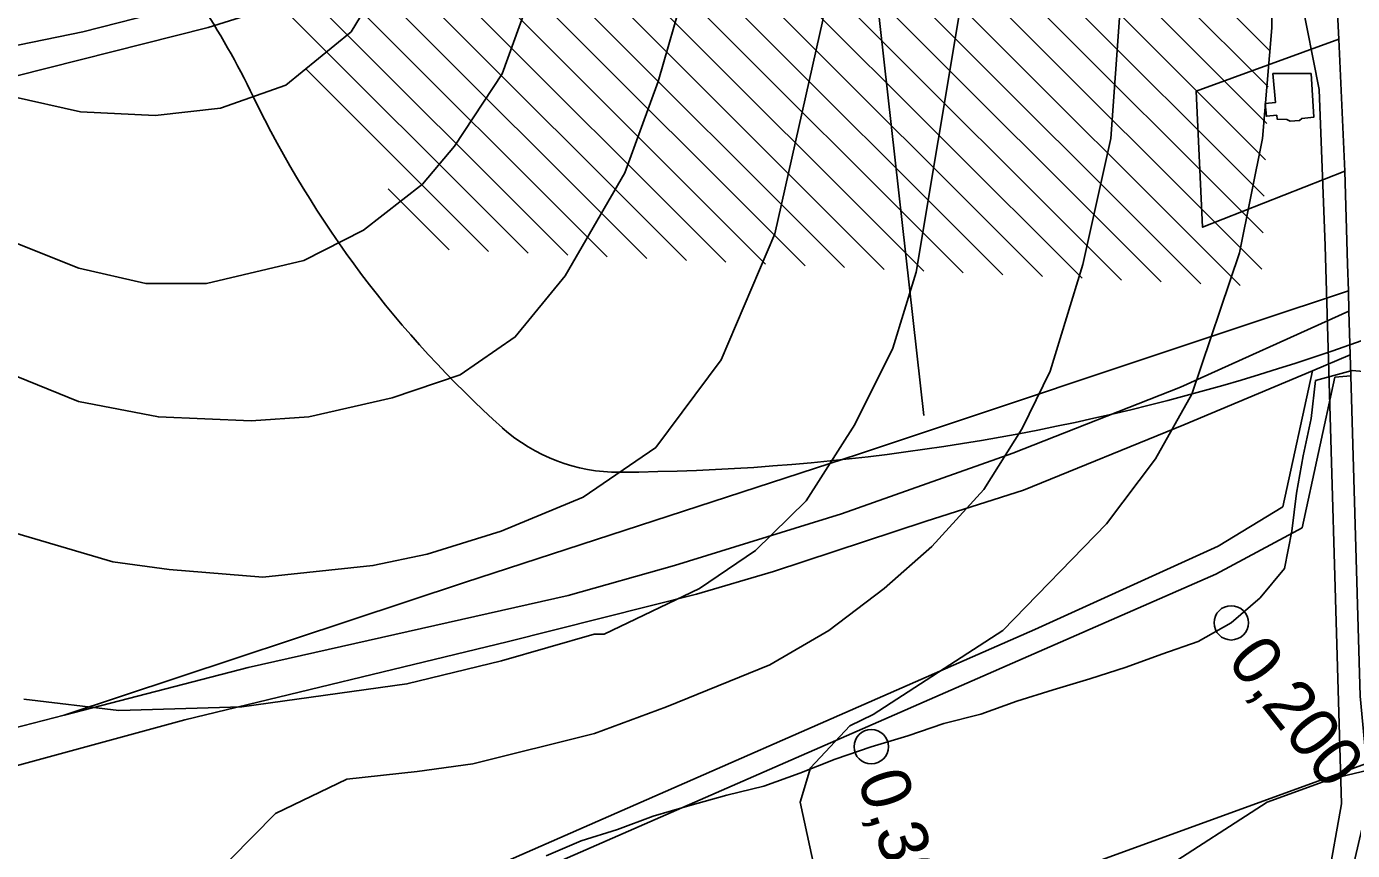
# Model space of a CAD drawing. Extents: x -510989 to -501240, y -1184665 to -1176089.
# Drawn here: x -509914.8 to -509567.3, y -1180046.7 to -1179830.6 of the extents above; entities that cross this region are included whole.
import ezdxf

# ---------------------------------------------------------------- set-up
doc = ezdxf.new("R2010")
doc.units = 0
for name, color, linetype in [('NAVRH_interakcni_prvky', 7, 'Continuous'), ('NAVRH_rozvodnice', 7, 'Continuous'), ('orna_puda', 7, 'Continuous'), ('ostatni_plocha_x_jina_plocha', 7, 'Continuous'), ('ostatni_plocha_x_silnice', 7, 'Continuous'), ('STAV_erozne_ohrozene_plochy', 7, 'Continuous'), ('STAV_systematicke_odvodneni', 7, 'Continuous'), ('trasovani_toku', 7, 'Continuous'), ('trvaly_travni_porost', 7, 'Continuous'), ('vodni_plocha_x_vodni_tok_v_koryt_prir_n_upr', 7, 'Continuous'), ('vrstevnice_01', 7, 'Continuous'), ('vrstevnice_02', 7, 'Continuous'), ('zastavena_plocha_a_nadvori', 7, 'Continuous')]:
    doc.layers.add(name, color=color, linetype=linetype)

msp = doc.modelspace()

# ---------------------------------------------------------------- linework, layer by layer
at = {"layer": 'NAVRH_interakcni_prvky'}
msp.add_line((-509697.84, -1179770.62), (-509679.58, -1179932.59), dxfattribs=at)
at = {"layer": 'NAVRH_rozvodnice'}
for centre, radius, start, end in [((-510050.65, -1179943.3), 216.87, 25.7756, 41.0092), ((-509602.53, -1179726.91), 280.76, 205.7756, 228.0907), ((-509763.21, -1179360.62), 586.9, 270.37632, 301.6654), ((-509759.66, -1179901.97), 45.53, 228.0907, 270.3763)]:
    msp.add_arc(centre, radius, start, end, dxfattribs=at)
at = {"layer": 'orna_puda'}
for points in [[(-509949.76, -1179823.34), (-509913.51, -1179813.75), (-509870.46, -1179802.75), (-509832.41, -1179791.08), (-509790.88, -1179777.39), (-509727.17, -1179755.55), (-509675.85, -1179735.34), (-509630, -1179719.89), (-509571.56, -1179700.19), (-509571.71, -1179702.48), (-509572.08, -1179708.08), (-509572.93, -1179721), (-509712.37, -1179771.32), (-509759.16, -1179788.2), (-509793.14, -1179799.75), (-509845.95, -1179815.81), (-509867.41, -1179823.72), (-509900.03, -1179832.04), (-509926.9, -1179837.49)], [(-509934.38, -1179847.85), (-509867.17, -1179830.91), (-509792.97, -1179807.66), (-509765.76, -1179799.13), (-509673.8, -1179764.23), (-509573.59, -1179731.06), (-509575.02, -1179752.72), (-509572.29, -1179751.86), (-509570.13, -1179751.18), (-509573.4, -1179783.55), (-509570.8, -1179833.9), (-509608.19, -1179847.61), (-509606.53, -1179883.25), (-509569.24, -1179868.59), (-509568.53, -1179892.94), (-509568.33, -1179899.97), (-509592.74, -1179908.1), (-509696.74, -1179942.74), (-509799.96, -1179976.4), (-509904.89, -1180011.19), (-509945.61, -1180021.74)], [(-509722.44, -1180081.65), (-509563.62, -1180023.92), (-509562.83, -1180032.49), (-509569.47, -1180061.07)]]:
    msp.add_lwpolyline(points, dxfattribs=at)
for points in [[(-509573.59, -1179731.06), (-509673.8, -1179764.23), (-509765.76, -1179799.13), (-509792.97, -1179807.66), (-509867.17, -1179830.91), (-509934.38, -1179847.85), (-509942.51, -1179849.9), (-509966.28, -1179853.46), (-510002.2, -1179858.21), (-510043.39, -1179861.58), (-510096.1, -1179867.95), (-510116.32, -1179858.81), (-510092.18, -1179857.59), (-509971.29, -1179844.16), (-509953.77, -1179842.93), (-509926.9, -1179837.49), (-509900.03, -1179832.04), (-509867.41, -1179823.72), (-509845.95, -1179815.81), (-509793.14, -1179799.75), (-509759.16, -1179788.2), (-509712.37, -1179771.32), (-509572.93, -1179721)], [(-509608.19, -1179847.61), (-509570.8, -1179833.9), (-509569.24, -1179868.59), (-509606.53, -1179883.25)], [(-509578.07, -1179842.92), (-509588.14, -1179842.96), (-509587.43, -1179850.54), (-509590.13, -1179850.79), (-509589.82, -1179854.15), (-509587.1, -1179853.9), (-509587.01, -1179854.9), (-509584.43, -1179855.05), (-509583.61, -1179855.48), (-509581.18, -1179855.31), (-509580.53, -1179854.75), (-509577.42, -1179854.43)]]:
    msp.add_lwpolyline(points, close=True, dxfattribs=at)
at = {"layer": 'ostatni_plocha_x_jina_plocha'}
msp.add_lwpolyline([(-509568.18, -1179905.23), (-509612.32, -1179925.23), (-509656.3, -1179942.52), (-509701.17, -1179958.45), (-509744.95, -1179971.98), (-509772.84, -1179979.82), (-509856.7, -1179998.71), (-509904.89, -1180011.19), (-509799.96, -1179976.4), (-509696.74, -1179942.74), (-509592.74, -1179908.1), (-509568.33, -1179899.97)], close=True, dxfattribs=at)
at = {"layer": 'ostatni_plocha_x_silnice'}
msp.add_lwpolyline([(-509565.24, -1180006.24), (-509567.68, -1179922.21), (-509567.84, -1179916.75), (-509568.18, -1179905.23), (-509568.33, -1179899.97), (-509568.53, -1179892.94), (-509569.24, -1179868.59), (-509570.8, -1179833.9), (-509573.4, -1179783.55), (-509570.13, -1179751.18), (-509569.79, -1179747.85), (-509564.2, -1179736.53)], dxfattribs=at)
at = {"layer": 'STAV_erozne_ohrozene_plochy'}
for p, q in [((-509880.83, -1179545.08), (-509589.01, -1179836.9)), ((-509886.79, -1179549.02), (-509589.35, -1179846.46)), ((-509892.75, -1179552.96), (-509589.69, -1179856.02)), ((-509898.71, -1179556.9), (-509590.03, -1179865.58)), ((-509904.67, -1179560.84), (-509590.37, -1179875.14)), ((-509910.63, -1179564.78), (-509590.71, -1179884.7)), ((-509916.58, -1179568.73), (-509591.05, -1179894.26)), ((-509922.54, -1179572.67), (-509596.68, -1179898.52)), ((-509928.5, -1179576.61), (-509607.05, -1179898.06)), ((-509934.46, -1179580.55), (-509617.42, -1179897.59)), ((-509937.21, -1179587.7), (-509627.79, -1179897.12)), ((-509937.11, -1179597.69), (-509638.15, -1179896.65)), ((-509937.02, -1179607.69), (-509648.52, -1179896.18)), ((-509936.93, -1179617.68), (-509658.89, -1179895.72)), ((-509936.83, -1179627.67), (-509669.26, -1179895.25)), ((-509936.74, -1179637.66), (-509679.62, -1179894.78)), ((-509936.65, -1179647.66), (-509689.99, -1179894.31)), ((-509936.54, -1179657.66), (-509700.36, -1179893.84)), ((-509931.47, -1179672.63), (-509710.73, -1179893.38)), ((-509926.4, -1179687.6), (-509721.09, -1179892.91)), ((-509921.33, -1179702.57), (-509731.46, -1179892.44)), ((-509916.26, -1179717.54), (-509741.83, -1179891.97)), ((-509911.19, -1179732.51), (-509752.2, -1179891.5)), ((-509905.49, -1179748.11), (-509762.56, -1179891.04)), ((-509884.12, -1179779.38), (-509772.93, -1179890.57)), ((-509862.74, -1179810.65), (-509783.3, -1179890.1)), ((-509841.37, -1179841.93), (-509793.67, -1179889.63)), ((-509820, -1179873.2), (-509804.03, -1179889.16))]:
    msp.add_line(p, q, dxfattribs=at)
at = {"layer": 'STAV_systematicke_odvodneni'}
for p, q in [((-509654.64, -1179442.96), (-509576.02, -1179847.16)), ((-509574.42, -1179888.14), (-509576.02, -1179847.16)), ((-509570.17, -1180034.49), (-509574.42, -1179888.14)), ((-509574.42, -1180058.44), (-509570.17, -1180034.49))]:
    msp.add_line(p, q, dxfattribs=at)
at = {"layer": 'trasovani_toku'}
for p, q in [((-509567.31, -1179920.81), (-509576.95, -1179923.46)), ((-509557.36, -1179921.77), (-509567.31, -1179920.81)), ((-509576.95, -1179923.46), (-509578.06, -1179933.4)), ((-509578.06, -1179933.4), (-509580.19, -1179943.17)), ((-509580.19, -1179943.17), (-509581.92, -1179953.02)), ((-509581.92, -1179953.02), (-509583.14, -1179962.95)), ((-509583.14, -1179962.95), (-509585.12, -1179972.75)), ((-509585.12, -1179972.75), (-509591.5, -1179980.45)), ((-509591.5, -1179980.45), (-509599.05, -1179987)), ((-509599.05, -1179987), (-509607.75, -1179991.93)), ((-509607.75, -1179991.93), (-509617.21, -1179995.17)), ((-509617.21, -1179995.17), (-509626.6, -1179998.62)), ((-509636.13, -1180001.66), (-509645.7, -1180004.55)), ((-509626.6, -1179998.62), (-509636.13, -1180001.66)), ((-509645.7, -1180004.55), (-509655.24, -1180007.54)), ((-509655.24, -1180007.54), (-509664.64, -1180010.96)), ((-509664.64, -1180010.96), (-509674.34, -1180013.41)), ((-509674.34, -1180013.41), (-509683.81, -1180016.59)), ((-509683.81, -1180016.59), (-509693.39, -1180019.49)), ((-509693.39, -1180019.49), (-509702.84, -1180022.75)), ((-509702.84, -1180022.75), (-509712.14, -1180026.42)), ((-509712.14, -1180026.42), (-509721.54, -1180029.84)), ((-509731.25, -1180032.22), (-509740.89, -1180034.89)), ((-509721.54, -1180029.84), (-509731.25, -1180032.22)), ((-509740.89, -1180034.89), (-509750.5, -1180037.67)), ((-509750.5, -1180037.67), (-509759.86, -1180041.17)), ((-509759.86, -1180041.17), (-509769.39, -1180044.2)), ((-509769.39, -1180044.2), (-509778.59, -1180048.11))]:
    msp.add_line(p, q, dxfattribs=at)
for centre in [(-509599.05, -1179987), (-509693.39, -1180019.49)]:
    msp.add_circle(centre, 4.5, dxfattribs=at)
at = {"layer": 'trvaly_travni_porost'}
for points in [[(-509567.84, -1179916.75), (-509577.76, -1179920.91), (-509611.45, -1179935.04), (-509653.5, -1179952.18), (-509678.96, -1179960.33), (-509718.99, -1179973.53), (-509739.2, -1179979.48), (-509788.78, -1179991.96), (-509873.26, -1180012.46), (-509935.83, -1180029.48), (-509943.23, -1180023.62), (-509945.61, -1180021.74), (-509904.89, -1180011.19), (-509856.7, -1179998.71), (-509772.84, -1179979.82), (-509744.95, -1179971.98), (-509701.17, -1179958.45), (-509656.3, -1179942.52), (-509612.32, -1179925.23), (-509568.18, -1179905.23)], [(-509577.76, -1179920.91), (-509585.54, -1179956.57), (-509602.46, -1179966.89), (-509650.52, -1179988.75), (-509793.49, -1180051.52), (-509971.9, -1180053.49), (-509968.29, -1180058.04), (-509984.1, -1180065.83), (-510004.89, -1180074.86), (-510003.01, -1180068.4), (-510001.04, -1180061.62), (-509988.64, -1180055.06), (-509988.89, -1180047.1), (-509981.94, -1180044.5), (-509981.36, -1180035.85), (-509943.23, -1180023.62), (-509935.83, -1180029.48), (-509873.26, -1180012.46), (-509788.78, -1179991.96), (-509739.2, -1179979.48), (-509718.99, -1179973.53), (-509678.96, -1179960.33), (-509653.5, -1179952.18), (-509611.45, -1179935.04)]]:
    msp.add_lwpolyline(points, close=True, dxfattribs=at)
msp.add_lwpolyline([(-509967.35, -1180059.23), (-509800.89, -1180057.29), (-509791.69, -1180055.81), (-509786.94, -1180054.7), (-509694.28, -1180014.14), (-509603.1, -1179974.24), (-509580.47, -1179962.08), (-509571.85, -1179922.59), (-509567.68, -1179922.21), (-509565.24, -1180006.24), (-509563.62, -1180023.92), (-509722.44, -1180081.65), (-509754.45, -1180090.32), (-509816.6, -1180104.43), (-509819.08, -1180096.5), (-509827.86, -1180088.44), (-509830.07, -1180080.34), (-509842.17, -1180079.77), (-509878.93, -1180085.53), (-509891.98, -1180088.58), (-509953.4, -1180109.7)], dxfattribs=at)
at = {"layer": 'vodni_plocha_x_vodni_tok_v_koryt_prir_n_upr'}
msp.add_lwpolyline([(-509567.84, -1179916.75), (-509567.68, -1179922.21), (-509571.85, -1179922.59), (-509580.47, -1179962.08), (-509603.1, -1179974.24), (-509694.28, -1180014.14), (-509786.94, -1180054.7), (-509791.69, -1180055.81), (-509800.89, -1180057.29), (-509967.35, -1180059.23), (-509968.29, -1180058.04), (-509971.9, -1180053.49), (-509793.49, -1180051.52), (-509650.52, -1179988.75), (-509602.46, -1179966.89), (-509585.54, -1179956.57), (-509577.76, -1179920.91)], close=True, dxfattribs=at)
at = {"layer": 'vrstevnice_01'}
for points in [[(-509702.69, -1179406), (-509699.09, -1179418), (-509697.81, -1179436), (-509698.5, -1179488), (-509703.81, -1179515), (-509717.19, -1179549), (-509721.41, -1179576), (-509720.69, -1179593), (-509714.91, -1179638), (-509715.81, -1179657), (-509731.5, -1179731), (-509733.81, -1179763), (-509742.31, -1179821), (-509749.19, -1179845), (-509758, -1179869), (-509773.59, -1179896), (-509786.69, -1179912), (-509801.09, -1179922), (-509818.91, -1179928), (-509840.81, -1179933), (-509855.91, -1179934), (-509880.19, -1179933), (-509901.19, -1179929), (-509930.69, -1179917)], [(-509868.41, -1179452), (-509805.09, -1179469), (-509796.09, -1179474), (-509788.31, -1179482), (-509784.69, -1179491), (-509785.41, -1179510), (-509790.5, -1179544), (-509790, -1179586), (-509786.31, -1179659), (-509788.31, -1179687), (-509793.41, -1179720), (-509809.91, -1179794), (-509820.59, -1179817), (-509829.69, -1179832), (-509846.81, -1179846), (-509863.91, -1179852), (-509881.09, -1179854), (-509900.59, -1179853), (-509918.5, -1179849)], [(-509563.5, -1179591), (-509569.5, -1179614), (-509575.59, -1179671), (-509585.69, -1179726), (-509588.19, -1179756), (-509588.41, -1179831), (-509590.81, -1179860), (-509596.91, -1179890), (-509609.41, -1179927), (-509618.91, -1179944), (-509631.69, -1179961), (-509658.91, -1179989), (-509692.91, -1180011), (-509699, -1180014), (-509709.31, -1180025), (-509712, -1180034), (-509708.31, -1180051)], [(-509670.09, -1179826), (-509681.59, -1179895), (-509687.69, -1179915), (-509697.69, -1179935), (-509710.41, -1179955), (-509723.69, -1179968), (-509738.41, -1179978), (-509763.41, -1179990), (-509766, -1179990), (-509790.31, -1179997), (-509815.09, -1180003), (-509858.31, -1180009), (-509890.59, -1180010), (-509915.5, -1180007)], [(-509617.5, -1180052), (-509589.59, -1180034), (-509573, -1180028), (-509560.59, -1180025), (-509556.5, -1179988), (-509547.91, -1179988), (-509539.5, -1179994), (-509535.19, -1180000), (-509491, -1179975), (-509485.09, -1179974), (-509479.09, -1179975), (-509470.31, -1179979), (-509461.81, -1179984), (-509453.31, -1179996), (-509447.81, -1180009), (-509445, -1180020), (-509443, -1180044), (-509444.5, -1180077)]]:
    msp.add_lwpolyline(points, dxfattribs=at)
at = {"layer": 'vrstevnice_02'}
for points in [[(-509656.31, -1179412), (-509657.31, -1179474), (-509664.19, -1179507), (-509679.19, -1179557), (-509681.91, -1179589), (-509679.59, -1179641), (-509681.91, -1179663), (-509694.41, -1179722), (-509698.69, -1179753), (-509706.09, -1179829), (-509718.69, -1179885), (-509732.69, -1179918), (-509749.81, -1179941), (-509768.91, -1179954), (-509790.41, -1179963), (-509809.81, -1179969), (-509824, -1179972), (-509852.81, -1179975), (-509877.41, -1179973), (-509892.19, -1179971), (-509919.41, -1179963)], [(-509861.31, -1180049), (-509849.5, -1180037), (-509830.81, -1180028), (-509812.41, -1180026), (-509797.81, -1180024), (-509765.91, -1180016), (-509747.09, -1180009), (-509720, -1179998), (-509704.5, -1179989), (-509690, -1179978), (-509677.5, -1179967), (-509663.91, -1179952), (-509653.81, -1179936), (-509646.5, -1179921), (-509637.91, -1179893), (-509630.59, -1179860), (-509627, -1179810)], [(-509936.19, -1179880), (-509901.09, -1179894), (-509883.5, -1179898), (-509867.59, -1179898), (-509842.09, -1179892), (-509826.5, -1179884), (-509811, -1179872), (-509802.59, -1179862), (-509790.09, -1179843), (-509778.59, -1179811)]]:
    msp.add_lwpolyline(points, dxfattribs=at)
at = {"layer": 'zastavena_plocha_a_nadvori'}
msp.add_lwpolyline([(-509578.07, -1179842.92), (-509577.42, -1179854.43), (-509580.53, -1179854.75), (-509581.18, -1179855.31), (-509583.61, -1179855.48), (-509584.43, -1179855.05), (-509587.01, -1179854.9), (-509587.1, -1179853.9), (-509589.82, -1179854.15), (-509590.13, -1179850.79), (-509587.43, -1179850.54), (-509588.14, -1179842.96)], close=True, dxfattribs=at)

# ---------------------------------------------------------------- texts
at = {"layer": 'trasovani_toku'}
for s, rotation, p in [('0,200', 308.2221, (-509600.44, -1179997.05)), ('0,300', 288.131, (-509697.12, -1180027.87))]:
    msp.add_text(s, height=13, rotation=rotation, dxfattribs=at).set_placement(p)

doc.saveas('drawing.dxf')
